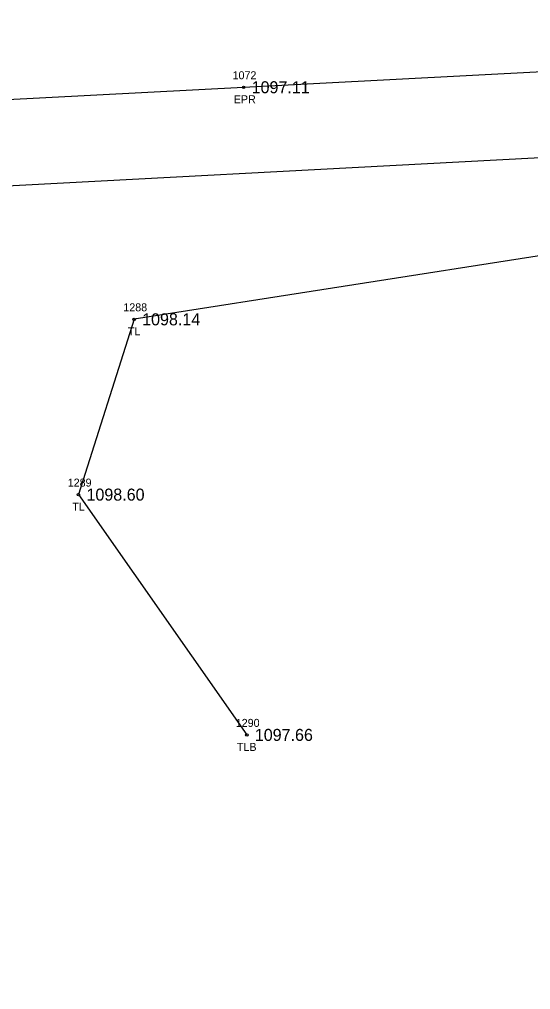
# Model space of a CAD drawing. Extents: x 1539151 to 1541799, y 1198646 to 1201165.
# Drawn here: x 1539579.5 to 1539643.3, y 1199238.5 to 1199359.7 of the extents above; entities that cross this region are included whole.
import ezdxf

# ---------------------------------------------------------------- set-up
doc = ezdxf.new("R2010")
doc.units = 0
for name, color, linetype in [('RD_EX_Road', 7, 'Continuous'), ('RD_EX_Road_txCode', 7, 'Continuous'), ('RD_EX_TX_Road_ELEV', 7, 'Continuous'), ('RD_EX_TX_VEG_ELEV', 7, 'Continuous'), ('RD_EX_VEG', 7, 'Continuous'), ('RD_EX_VEG_txCode', 7, 'Continuous'), ('RD_SMD_Locator', 7, 'Continuous')]:
    doc.layers.add(name, color=color, linetype=linetype)

msp = doc.modelspace()

# ---------------------------------------------------------------- linework, layer by layer
at = {"layer": 'RD_EX_Road'}
msp.add_lwpolyline([(1539376.14, 1199238.5), (1539389.65, 1199292.82), (1539395.62, 1199315.5), (1539405.98, 1199330.34), (1539420.48, 1199338.44), (1539434.13, 1199341.92), (1539458.27, 1199343.35), (1539505.21, 1199345.92), (1539518.44, 1199346.66), (1539558.02, 1199348.62), (1539607.46, 1199351.19), (1539654.3, 1199353.64), (1539676.57, 1199355), (1539708.42, 1199356.93), (1539757.47, 1199359.08), (1539779.44, 1199360.44), (1539802.8, 1199361.54), (1539858.43, 1199364.46), (1539908.44, 1199366.95), (1539925.86, 1199367.85), (1539963.35, 1199372.53)], dxfattribs=at)
at = {"layer": 'RD_EX_VEG'}
msp.add_lwpolyline([(1539549.37, 1199266.39), (1539527.74, 1199289.41), (1539527.1, 1199327.64), (1539552.79, 1199337.55), (1539657.87, 1199343.12), (1539645.98, 1199330.41), (1539593.79, 1199322.21), (1539586.84, 1199300.32), (1539607.86, 1199270.31)], dxfattribs=at)
at = {"layer": 'RD_SMD_Locator'}
for centre in [(1539607.46, 1199351.19), (1539593.79, 1199322.21), (1539586.84, 1199300.32), (1539607.86, 1199270.31)]:
    msp.add_circle(centre, 0.15, dxfattribs=at)

# ---------------------------------------------------------------- texts
at = {"layer": 'RD_EX_Road_txCode'}
for s, p in [('1072', (1539606.08, 1199352.19)), ('EPR', (1539606.23, 1199349.19))]:
    msp.add_text(s, height=1, dxfattribs=at).set_placement(p)
at = {"layer": 'RD_EX_TX_Road_ELEV'}
msp.add_text('1097.11', height=1.5, dxfattribs=at).set_placement((1539608.46, 1199350.44))
at = {"layer": 'RD_EX_TX_VEG_ELEV'}
for s, p in [('1098.14', (1539594.79, 1199321.46)), ('1098.60', (1539587.84, 1199299.57)), ('1097.66', (1539608.86, 1199269.56))]:
    msp.add_text(s, height=1.5, dxfattribs=at).set_placement(p)
at = {"layer": 'RD_EX_VEG_txCode'}
for s, p in [('1288', (1539592.44, 1199323.21)), ('TL', (1539593.01, 1199320.21)), ('1289', (1539585.5, 1199301.32)), ('TL', (1539586.07, 1199298.32)), ('1290', (1539606.48, 1199271.31)), ('TLB', (1539606.62, 1199268.31))]:
    msp.add_text(s, height=1, dxfattribs=at).set_placement(p)

doc.saveas('drawing.dxf')
